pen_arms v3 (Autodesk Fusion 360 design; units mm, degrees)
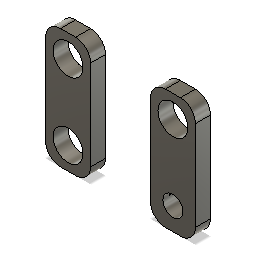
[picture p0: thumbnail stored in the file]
sketch "Sketch1" plane through (0, 0, 0) normal (0, 0, 1) x axis (1, 0, 0)
  line L1 (25, 5) -> (10, 5)
  line L2 (25, 45) -> (25, 5)
  line L3 (10, 45) -> (25, 45)
  line L4 (10, 5) -> (10, 45)
  line L5 (17.5, -20) -> (17.5, 45)
  line L6 (40, 25) -> (10, 25)
  line L7 (60, 45) -> (60, 5)
  line L8 (75, 25) -> (45, 25)
  line L9 (60, 5) -> (45, 5)
  line L10 (45, 5) -> (45, 45)
  line L11 (45, 45) -> (60, 45)
  line L12 (52.5, -25) -> (52.5, 37.5)
  line L13 (61, 12.5) -> (17.5, 12.5)
  circle C1 centre (17.5, 12.5) radius 5
  circle C2 centre (17.5, 37.5) radius 5
  circle C3 centre (52.5, 37.5) radius 5
  circle C4 centre (52.5, 12.5) radius 3.35
  point P6 (17.5, 45)
  point P8 (17.5, 12.5)
  point P9 (17.5, 37.5)
  point P10 (10, 25)
  point P14 (52.5, 45)
  point P13 (45, 25)
  point P18 (52.5, 37.5)
  point P21 (52.5, 37.5)
  point P23 (17.5, 12.5)
  point P25 (52.5, 12.5)
  point P4 (25, 45)
  point P5 (10, 45)
  point P2 (10, 5)
  point P15 (60, 45)
  point P17 (45, 45)
  point P16 (45, 5)
  horizontal L1
  vertical L2
  horizontal L3
  vertical L4
  midpoint L3 P6
  perpendicular L3 L5
  midpoint L5 P8
  coincident L5 P9
  midpoint L4 P10
  perpendicular L5 L6
  symmetric C1 C2 L6
  horizontal L9
  vertical L7
  horizontal L11
  vertical L10
  midpoint P14 L11
  midpoint P13 L10
  coincident P18 P21
  perpendicular L9 L12
  coincident P8 P23
  perpendicular L7 L13
  coincident L12 P25
  coincident L13 P25
  dimension "d1" distance P4 P5 = 15
  dimension "d2" distance P2 P5 = 40
  dimension "d3" diameter C1 = 10
  dimension "d4" diameter C2 = 10
  dimension "d9" distance P15 P17 = 15
  dimension "d10" distance P16 P17 = 40
  dimension "d12" diameter C3 = 10
  dimension "d18" distance P8 P9 = 25
  dimension "d19" distance P18 P25 = 25
  dimension "d20" diameter C4 = 6.7
extrude "Extrude1" new body sketch "Sketch1" profile of L1 L2 L3 L4 C1 C2 along normal blind 5
fillet "Fillet1" radius 5
extrude "Extrude2" new body sketch "Sketch1" profile of L7 L9 L10 L11 C3 C4 along normal blind 5
fillet "Fillet2" radius 5
sketch "Sketch4" plane through (0, 0, 0) normal (0, 0, 1) x axis (1, 0, 0)
  line L1 (49.1683, 12.8497) -> (50.7098, 27.5379)
  line L2 (50, 5) -> (55, 5)
  line L3 (45, 40) -> (45, 10)
  line L4 (55, 45) -> (50, 45)
  line L5 (60, 10) -> (60, 40)
  line L6 (55.8317, 12.8497) -> (54.2902, 27.5379)
  circle C1 centre (52.5, 27.35) radius 1.8
  circle C2 centre (52.5, 37.5) radius 5
  circle C3 centre (52.5, 12.5) radius 3.35
  arc A1 centre (55, 10) radius 5 clockwise from (60, 10) to (55, 5)
  arc A2 centre (50, 10) radius 5 clockwise from (50, 5) to (45, 10)
  arc A3 centre (50, 40) radius 5 clockwise from (45, 40) to (50, 45)
  arc A4 centre (55, 40) radius 5 clockwise from (55, 45) to (60, 40)
  circle C4 centre (52.5, 12.5) radius 3.35
  point P3 (50.7098, 27.5379)
  point P2 (52.5, 27.35)
  point P20 (52.5, 12.5)
  point P21 (52.5, 9.15)
  point P22 (52.5, 29.15)
  point P23 (54.2902, 27.5379)
  point P24 (55.8317, 12.8497)
  point P4 (49.1683, 12.8497)
  coincident C1 P3
  tangent C1 L1
  tangent L1 C4
  vertical P2 P20
  coincident C3 P21
  vertical P20 P21
  coincident C1 P22
  vertical P20 P22
  coincident C1 P23
  coincident C3 P24
  tangent C3 L6
  tangent C1 L6
  coincident P4 C4
  coincident C4 P24
  dimension "d21" distance P21 P22 = 20
  dimension "d22" diameter C1 = 3.6
extrude "Extrude3" cut sketch "Sketch4" profile of C1 L1 C3 C4 L6 along normal blind 3
sketch "Sketch5" plane through (0, 0, 0) normal (0, 0, -1) x axis (-1, 0, 0)
  line L1 (-50, 5) -> (-55, 5)
  line L2 (-45, 40) -> (-45, 10)
  line L3 (-55, 45) -> (-50, 45)
  line L4 (-60, 10) -> (-60, 40)
  line L5 (-54.2902, 27.5379) -> (-55.8317, 12.8497)
  line L6 (-49.1683, 12.8497) -> (-50.7098, 27.5379)
  arc A1 centre (-55, 10) radius 5 clockwise from (-55, 5) to (-60, 10)
  arc A2 centre (-50, 10) radius 5 clockwise from (-45, 10) to (-50, 5)
  arc A3 centre (-50, 40) radius 5 clockwise from (-50, 45) to (-45, 40)
  arc A4 centre (-55, 40) radius 5 clockwise from (-60, 40) to (-55, 45)
  arc A5 centre (-52.5, 27.35) radius 1.8 clockwise from (-54.2902, 27.5379) to (-50.7098, 27.5379)
  arc A6 centre (-52.5, 12.5) radius 3.35 clockwise from (-49.1683, 12.8497) to (-55.8317, 12.8497)
  circle C1 centre (-52.5, 37.5) radius 5
sketch "Sketch2" plane through (0, 0, 5) normal (0, 0, 1) x axis (1, 0, 0)
  line L1 (20, 5) -> (15, 5)
  line L2 (25, 40) -> (25, 10)
  line L3 (15, 45) -> (20, 45)
  line L4 (10, 10) -> (10, 40)
  arc A1 centre (15, 10) radius 5 clockwise from (15, 5) to (10, 10)
  arc A2 centre (20, 10) radius 5 clockwise from (25, 10) to (20, 5)
  arc A3 centre (20, 40) radius 5 clockwise from (20, 45) to (25, 40)
  arc A4 centre (15, 40) radius 5 clockwise from (10, 40) to (15, 45)
  circle C1 centre (17.5, 12.5) radius 5
  circle C2 centre (17.5, 37.5) radius 5
sketch "Sketch3" plane through (0, 0, 5) normal (0, 0, 1) x axis (1, 0, 0)
  line L1 (60, 40) -> (60, 10)
  line L2 (50, 45) -> (55, 45)
  line L3 (45, 10) -> (45, 40)
  line L4 (55, 5) -> (50, 5)
  arc A1 centre (55, 10) radius 5 clockwise from (60, 10) to (55, 5)
  arc A2 centre (55, 40) radius 5 clockwise from (55, 45) to (60, 40)
  arc A3 centre (50, 40) radius 5 clockwise from (45, 40) to (50, 45)
  arc A4 centre (50, 10) radius 5 clockwise from (50, 5) to (45, 10)
  circle C1 centre (52.5, 37.5) radius 5
  circle C2 centre (52.5, 12.5) radius 3.35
